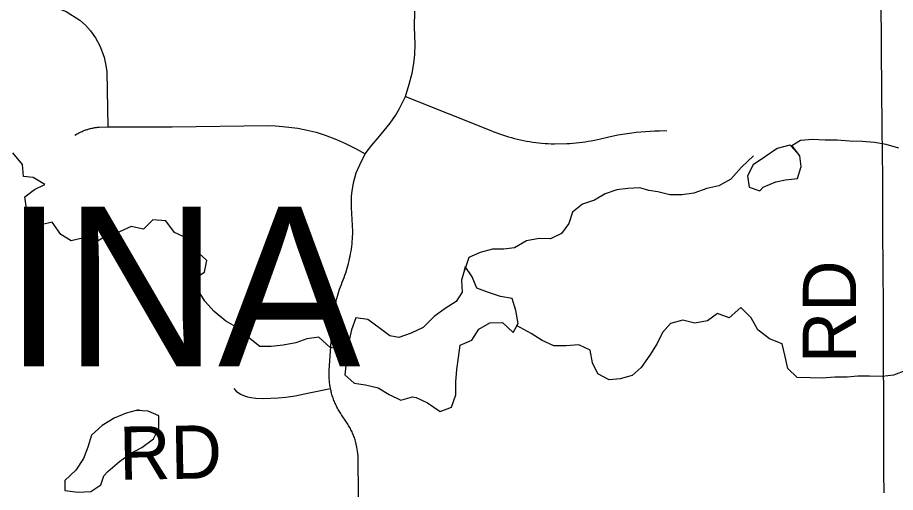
# Model space of a CAD drawing. Extents: x 0 to 34, y 0 to 22.
# Drawn here: x 5.1166 to 5.5847, y 16.8292 to 17.0826 of the extents above; entities that cross this region are included whole.
import ezdxf

# ---------------------------------------------------------------- set-up
doc = ezdxf.new("R2010")
doc.units = 0
for name, color, linetype in [('GM_X_County_Road_Text', 7, 'Continuous'), ('GM_X_Minor_Lake', 7, 'Continuous'), ('GM_X_Minor_River', 7, 'Continuous'), ('GM_X_Township_Road', 7, 'Continuous'), ('GM_X_Township_Road_Text', 7, 'Continuous'), ('GM_X_Township_Text', 7, 'Continuous')]:
    doc.layers.add(name, color=color, linetype=linetype)

msp = doc.modelspace()

# ---------------------------------------------------------------- linework, layer by layer
at = {"layer": 'GM_X_Minor_Lake'}
for points in [[(5.5289, 17.01416), (5.52836, 17.01444), (5.52155, 17.01273), (5.51531, 17.00855), (5.50888, 17.00399), (5.50586, 16.99811), (5.50662, 16.99204), (5.51229, 16.99015)], [(5.51229, 16.99015), (5.51418, 16.99205), (5.52099, 16.99489), (5.5261, 16.99603), (5.53253, 16.9968), (5.53442, 17.00306), (5.53366, 17.00875), (5.52968, 17.01425)], [(5.51229, 16.99015), (5.51418, 16.99205), (5.52099, 16.99489), (5.5261, 16.99603), (5.53253, 16.9968), (5.53442, 17.00306), (5.53366, 17.00875), (5.5289, 17.01416)], [(5.35532, 16.94985), (5.35532, 16.94928), (5.35324, 16.94245), (5.35362, 16.936), (5.35041, 16.93107), (5.34455, 16.92727), (5.33868, 16.92309), (5.33282, 16.91721), (5.32639, 16.91417), (5.31996, 16.91189), (5.31504, 16.91284), (5.30937, 16.91701), (5.30331, 16.92156), (5.29688, 16.92231), (5.29462, 16.91605), (5.29329, 16.9096), (5.29216, 16.90334), (5.29179, 16.89841), (5.29103, 16.89196), (5.29614, 16.88741), (5.30219, 16.88665), (5.30881, 16.88494), (5.31468, 16.88153), (5.32092, 16.8785), (5.32716, 16.88021)], [(5.35488, 16.9476), (5.35532, 16.94928), (5.35324, 16.94245), (5.35362, 16.936), (5.35041, 16.93107), (5.34455, 16.92727), (5.33868, 16.92309), (5.33282, 16.91721), (5.32639, 16.91417), (5.31996, 16.91189), (5.31504, 16.91284), (5.30937, 16.91701), (5.30331, 16.92156), (5.29688, 16.92231), (5.29462, 16.91605), (5.29329, 16.9096), (5.29216, 16.90334), (5.29179, 16.89841), (5.29103, 16.89196), (5.29614, 16.88741), (5.30219, 16.88665), (5.30881, 16.88494), (5.31468, 16.88153), (5.32092, 16.8785), (5.32716, 16.88021)], [(5.32716, 16.88021), (5.32905, 16.87983), (5.33511, 16.87699), (5.34192, 16.87244), (5.34797, 16.87472), (5.35024, 16.88136), (5.35024, 16.88819), (5.3508, 16.89483), (5.35174, 16.90128), (5.3525, 16.90773), (5.35874, 16.91039), (5.36252, 16.91627), (5.36838, 16.91969), (5.37519, 16.91989), (5.38087, 16.91458), (5.38351, 16.91932), (5.38219, 16.92634), (5.38029, 16.9326), (5.37405, 16.93373), (5.36762, 16.93582), (5.36156, 16.93828), (5.35891, 16.94416), (5.35532, 16.94985)], [(5.18134, 16.87331), (5.17453, 16.87141), (5.1681, 16.86875), (5.16167, 16.86495), (5.15599, 16.85983), (5.15411, 16.85338), (5.15165, 16.8473), (5.14768, 16.84104), (5.14182, 16.83554), (5.14182, 16.83022), (5.14882, 16.82928), (5.15563, 16.82966), (5.16092, 16.83327), (5.16262, 16.83801)], [(5.17982, 16.87293), (5.17453, 16.87141), (5.1681, 16.86875), (5.16167, 16.86495), (5.15599, 16.85983), (5.15411, 16.85338), (5.15165, 16.8473), (5.14768, 16.84104), (5.14182, 16.83554), (5.14182, 16.83022), (5.14882, 16.82928), (5.15563, 16.82966), (5.16092, 16.83327), (5.16262, 16.83801)], [(5.16262, 16.83801), (5.1647, 16.84029), (5.17094, 16.84561), (5.17681, 16.84997), (5.18286, 16.8532), (5.1891, 16.85776), (5.19193, 16.86345), (5.19193, 16.87009), (5.18625, 16.87255), (5.17982, 16.87293)]]:
    msp.add_lwpolyline(points, dxfattribs=at)
at = {"layer": 'GM_X_Minor_River'}
for points in [[(5.58653, 17.01291), (5.57968, 17.01484), (5.5736, 17.01603), (5.56716, 17.01645), (5.56016, 17.01667), (5.55353, 17.01727), (5.54729, 17.01713), (5.54048, 17.01754), (5.53406, 17.01701), (5.52936, 17.01416)], [(5.29222, 16.90494), (5.28321, 16.90648), (5.27722, 16.91204), (5.27081, 16.91113), (5.26499, 16.9091), (5.25822, 16.9078), (5.2518, 16.90708), (5.24575, 16.90713), (5.23978, 16.91193), (5.23456, 16.91674), (5.22767, 16.92057), (5.2215, 16.92574), (5.21645, 16.93131), (5.21291, 16.93711), (5.21069, 16.94332), (5.21629, 16.94668), (5.21747, 16.95296), (5.21109, 16.95889), (5.20679, 16.96486), (5.20029, 16.96793), (5.19561, 16.97409), (5.18879, 16.97469), (5.1838, 16.96964), (5.17715, 16.97119), (5.17097, 16.96821), (5.16439, 16.96654), (5.15843, 16.96279), (5.15195, 16.96511), (5.14518, 16.96344), (5.13961, 16.96691), (5.13511, 16.97345), (5.1291, 16.97198), (5.12393, 16.97452), (5.12133, 16.98072), (5.12043, 16.98696), (5.12564, 16.99087), (5.13106, 16.99346), (5.12492, 16.99731), (5.1198, 16.99776), (5.11928, 17.0042), (5.11403, 17.01034)], [(5.50891, 17.00884), (5.50262, 17.00281), (5.4969, 16.99642), (5.49055, 16.99286), (5.48416, 16.99138), (5.47722, 16.98895), (5.47081, 16.98804), (5.46438, 16.98808), (5.45791, 16.98964), (5.45317, 16.99029), (5.44841, 16.99169), (5.44199, 16.99136), (5.43614, 16.99065), (5.42995, 16.98861), (5.42417, 16.98525), (5.41779, 16.98302), (5.4124, 16.97872), (5.41046, 16.97279), (5.40661, 16.96739), (5.40081, 16.9646), (5.39476, 16.96465), (5.38798, 16.96355), (5.38164, 16.95979), (5.37579, 16.95909), (5.36974, 16.95895), (5.36316, 16.95728), (5.35718, 16.95449), (5.35488, 16.9476)], [(5.59021, 16.89423), (5.58365, 16.8918), (5.57761, 16.89109), (5.5708, 16.89131), (5.56456, 16.89117), (5.5589, 16.89066), (5.55228, 16.8907), (5.54568, 16.89016), (5.53924, 16.89039), (5.53224, 16.89061), (5.52722, 16.89524), (5.52593, 16.90166), (5.52426, 16.90845), (5.51758, 16.91114), (5.51123, 16.91593), (5.50768, 16.9223), (5.50226, 16.92786), (5.49596, 16.92241), (5.48985, 16.92473), (5.48446, 16.92081), (5.47768, 16.91952), (5.4714, 16.92108), (5.46482, 16.91941), (5.4604, 16.91456), (5.4577, 16.90862), (5.45368, 16.90246), (5.4491, 16.8959), (5.44428, 16.89161), (5.4379, 16.88976), (5.43205, 16.88924), (5.42592, 16.89252), (5.42314, 16.89833), (5.42185, 16.90513), (5.41592, 16.90803), (5.40913, 16.9075), (5.40251, 16.90734), (5.39639, 16.91024), (5.39044, 16.91408), (5.38263, 16.91825)]]:
    msp.add_lwpolyline(points, dxfattribs=at)
at = {"layer": 'GM_X_Township_Road'}
for points in [[(5.57861, 16.82899), (5.57857, 16.83969), (5.57851, 16.85553), (5.57844, 16.8703), (5.57835, 16.90812), (5.57826, 16.92833), (5.57801, 16.96897), (5.57789, 16.99756), (5.57773, 17.00965), (5.57764, 17.02402), (5.57731, 17.06478), (5.57706, 17.09543), (5.57681, 17.12318), (5.57672, 17.14112), (5.57647, 17.18213), (5.57638, 17.21025), (5.57641, 17.23871), (5.57627, 17.26882), (5.57549, 17.32956)], [(5.02251, 17.08065), (5.04235, 17.09995), (5.04504, 17.10207), (5.04795, 17.10376), (5.05098, 17.10543), (5.05425, 17.10644), (5.05778, 17.10725), (5.06089, 17.10748), (5.06488, 17.10738), (5.06792, 17.10695), (5.07034, 17.1063), (5.08334, 17.10267), (5.13654, 17.08812), (5.14255, 17.08585), (5.14973, 17.08125), (5.15284, 17.07859), (5.15552, 17.07557), (5.15818, 17.07188), (5.16053, 17.0676), (5.16275, 17.06153), (5.16372, 17.05697), (5.1642, 17.05363), (5.16476, 17.02423)], [(5.29845, 16.82689), (5.29818, 16.84863), (5.29791, 16.85128), (5.29756, 16.85329), (5.2968, 16.85654), (5.2966, 16.85718), (5.29639, 16.8578), (5.29617, 16.85843), (5.29594, 16.85905), (5.29569, 16.85966), (5.29544, 16.86027), (5.29518, 16.86088), (5.29491, 16.86148), (5.29462, 16.86208), (5.29432, 16.86267), (5.29402, 16.86326), (5.2937, 16.86384), (5.29338, 16.86441), (5.29304, 16.86499), (5.2927, 16.86555), (5.29234, 16.86611), (5.29194, 16.86672), (5.28925, 16.87068), (5.28887, 16.87126), (5.28851, 16.87182), (5.28817, 16.87238), (5.28783, 16.87295), (5.28751, 16.87353), (5.28719, 16.87411), (5.28688, 16.87469), (5.28659, 16.87528), (5.2863, 16.87588), (5.28603, 16.87648), (5.28577, 16.87709), (5.28551, 16.8777), (5.28527, 16.87831), (5.28504, 16.87894), (5.28481, 16.87956), (5.2846, 16.88018), (5.2844, 16.88082), (5.28421, 16.88145), (5.28404, 16.88209), (5.28387, 16.88273), (5.28372, 16.88337), (5.28357, 16.88402), (5.28344, 16.88466), (5.28326, 16.88568), (5.28315, 16.88634), (5.28306, 16.88699), (5.28298, 16.88765), (5.28291, 16.88831), (5.28285, 16.88896), (5.28281, 16.88962), (5.28278, 16.89028), (5.28281, 16.89425), (5.28425, 16.91746), (5.28442, 16.9196), (5.28455, 16.92092), (5.2847, 16.92223), (5.28488, 16.92354), (5.28508, 16.92485), (5.2853, 16.92616), (5.28555, 16.92746), (5.28581, 16.92875), (5.28611, 16.93004), (5.28642, 16.93133), (5.28676, 16.93261), (5.28711, 16.93388), (5.28749, 16.93515), (5.2879, 16.93641), (5.28832, 16.93766), (5.28877, 16.93891), (5.28924, 16.94014), (5.28973, 16.94137), (5.29022, 16.9426), (5.29069, 16.94384), (5.29113, 16.94509), (5.29156, 16.94634), (5.29196, 16.9476), (5.29234, 16.94887), (5.2927, 16.95014), (5.29304, 16.95142), (5.29335, 16.9527), (5.29364, 16.95399), (5.29391, 16.95529), (5.29416, 16.95659), (5.29438, 16.9579), (5.29458, 16.9592), (5.29476, 16.96051), (5.29491, 16.96183), (5.29504, 16.96314), (5.29515, 16.96446), (5.29523, 16.96578), (5.29529, 16.9671), (5.29533, 16.96843), (5.29499, 16.97492), (5.29461, 16.98127), (5.29472, 16.98723), (5.29505, 16.99002), (5.2957, 16.99439), (5.29718, 16.99975), (5.2991, 17.00408), (5.30194, 17.00987), (5.30555, 17.01458), (5.30883, 17.01846), (5.31523, 17.02623), (5.31819, 17.03044), (5.32032, 17.03416), (5.32344, 17.04051), (5.32546, 17.04712), (5.32699, 17.05303), (5.32792, 17.05812), (5.32841, 17.06288), (5.32858, 17.06824), (5.3283, 17.07764), (5.32841, 17.08612)], [(5.32344, 17.04051), (5.36899, 17.02226), (5.37053, 17.02165), (5.37207, 17.02107), (5.37363, 17.02051), (5.37519, 17.01998), (5.37676, 17.01947), (5.37835, 17.019), (5.37994, 17.01855), (5.38154, 17.01813), (5.38314, 17.01774), (5.38476, 17.01737), (5.38638, 17.01704), (5.38801, 17.01673), (5.38964, 17.01645), (5.39127, 17.0162), (5.39291, 17.01598), (5.39456, 17.01578), (5.39621, 17.01562), (5.39786, 17.01548), (5.39951, 17.01537), (5.40117, 17.01529), (5.40283, 17.01523), (5.40944, 17.01533), (5.41109, 17.01542), (5.41273, 17.01555), (5.41438, 17.01571), (5.41601, 17.01589), (5.41764, 17.0161), (5.41928, 17.01635), (5.4209, 17.01662), (5.42252, 17.01692), (5.42413, 17.01725), (5.42733, 17.01798), (5.4319, 17.01904), (5.43432, 17.01954), (5.43674, 17.01999), (5.43918, 17.02041), (5.44161, 17.02078), (5.44406, 17.0211), (5.44651, 17.02139), (5.44897, 17.02163), (5.45143, 17.02183), (5.4539, 17.02198), (5.45637, 17.02209), (5.45884, 17.02215), (5.46283, 17.02227)], [(5.14712, 17.01983), (5.14794, 17.02033), (5.14837, 17.02058), (5.1488, 17.02082), (5.14924, 17.02105), (5.14968, 17.02128), (5.15013, 17.02149), (5.15057, 17.0217), (5.15103, 17.0219), (5.15148, 17.0221), (5.15194, 17.02228), (5.15241, 17.02246), (5.15287, 17.02263), (5.15334, 17.02279), (5.15381, 17.02294), (5.15429, 17.02308), (5.15476, 17.02322), (5.15524, 17.02335), (5.15572, 17.02347), (5.1562, 17.02358), (5.15669, 17.02368), (5.15718, 17.02377), (5.15766, 17.02386), (5.15815, 17.02394), (5.15865, 17.024), (5.15914, 17.02407), (5.15963, 17.02412), (5.16012, 17.02416), (5.16476, 17.02423), (5.1991, 17.02431), (5.25001, 17.02494), (5.25416, 17.02481), (5.25801, 17.0245), (5.26607, 17.02355), (5.27102, 17.02253), (5.27573, 17.02146), (5.28056, 17.01989), (5.28672, 17.01761), (5.29152, 17.01536), (5.29715, 17.01265), (5.30194, 17.00987)], [(5.23186, 16.88466), (5.23317, 16.88323), (5.23543, 16.8817), (5.23752, 16.88069), (5.23925, 16.88022), (5.24094, 16.87991), (5.24362, 16.87956), (5.24762, 16.87936), (5.25551, 16.87959), (5.25966, 16.88001), (5.26453, 16.88079), (5.27212, 16.88233), (5.28344, 16.88466)]]:
    msp.add_lwpolyline(points, dxfattribs=at)

# ---------------------------------------------------------------- texts
at = {"layer": 'GM_X_County_Road_Text'}
msp.add_text('RD', height=0.028409, rotation=0.9872, dxfattribs=at).set_placement((5.17093, 16.83586))
at = {"layer": 'GM_X_Township_Road_Text'}
msp.add_text('RD', height=0.028409, rotation=90, dxfattribs=at).set_placement((5.56368, 16.89813))
at = {"layer": 'GM_X_Township_Text'}
msp.add_text('MEDINA', height=0.085227, rotation=0, dxfattribs=at).set_placement((4.85624, 16.89648))

doc.saveas('drawing.dxf')
